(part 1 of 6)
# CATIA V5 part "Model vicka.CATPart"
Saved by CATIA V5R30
Part number: Tvarnik_tvarnice
Material "PVC": density 1400 kg/m3, Young's modulus 3e+09 Pa, Poisson ratio 0.4, thermal expansion 9e-05 1/K
Bounding box of the stored display mesh (mm): x -12.5 to 2.6, y -74.249 to 75.778, z -73.2 to 71.421
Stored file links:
  E:\Bakalarka\Model\Vicko.CATPart
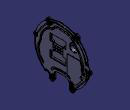
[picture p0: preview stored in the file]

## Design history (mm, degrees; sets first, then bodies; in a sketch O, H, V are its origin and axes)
WSupportSet1
Body1 "Vicko" (main body), material "PVC"
  Sketch1 on yz-plane, origin (0, 0, 0), H (0, 1, 0), V (0, 0, 1)
    circle A1 centre (0, 0) radius 71.425
    radius A1 = 71.425
  Pad1: profile Sketch1, direction (1, 0, 0), length 1.6
  Sketch2 on end face of Pad1, origin (1.6, 0, 0), H (0, 1, 0), V (0, 0, 1)
    point P1 (0, -48.7537)
    point P2 (4.8105, -22.8909)
    point P3 (2.4617, -31.9059)
    line L1 (19.7, -77.5722) -> (19.7, -54.5084)
    point P5 (19.7, -54.5084)
    point P6 (19.7, -54.5084)
    arc A1 centre (10.55, -54.5084) radius 9.15 from (19.7, -54.5084) to (12.2, -45.5084) ccw
    point P8 (12.2, -45.5084)
    point P9 (-13.7, -45.2166)
    arc A2 centre (-12.6167, -52.2166) radius 7.0833 from (-13.7, -45.2166) to (-19.7, -52.2166) ccw
    point P11 (-19.7, -52.2166)
    line L2 (-19.7, -52.2166) -> (-19.7, -86.8828)
    line L3 (-19.7, -86.8828) -> (19.7, -86.8828)
    point P13 (19.7, -86.8828)
    line L4 (19.7, -86.8828) -> (19.7, -77.5722)
    arc A3 centre (-1.5593, -117.2) radius 73 from (-13.7, -45.2166) to (12.2, -45.5084) cw
    point P15 (-13.7, -45.2166)
    distance L1 V = 19.7
    length L3 = 39.4
    distance P11 P5 H = 39.4
    distance P6 P5 H = 0
    distance P6 P5 = 0
    distance P9 P15 H = 0
    distance P9 P15 V = 0
    distance A3 H = 44.2
    distance L3 H = 86.8828
    distance P8 P5 H = 7.5
    distance P5 P8 V = 9
    distance P11 P9 V = 7
    length L2 = 34.6662
    distance P11 P9 H = 6
    radius A3 = 73
    vertical: L1 V, L4 V
    coincidence: P13 L1
    horizontal: L3 H
    tangency: A1 L1, A2 L2
  Pocket1: profile Sketch2, direction (-1, 0, 0), length 1.6
  Sketch3 on start face of Pad1, origin (0, 0, 0), H (0, -1, 0), V (0, 0, 1)
    line L1 (19.7, -73.2) -> (31.75, -73.2)
    line L2 (31.75, -73.2) -> (31.75, -53.2)
    line L3 (31.75, -53.2) -> (19.7, -53.2)
    line L4 (19.7, -53.2) -> (19.7, -73.2)
    reference projected line E1 (19.7, -52.2166) -> (19.7, -68.6545) from edge [face of Pocket1 from Sketch2.L2 | start face of Pad1]
    reference projected arc E2 centre (1.5593, -117.2) radius 73 from (13.7, -45.2166) to (-12.2, -45.5084) ccw from edge [face of Pocket1 from Sketch2.A3 | start face of Pad1]
    distance L4 E1 = 0
    distance E2 L1 = 29
    length L1 = 12.05
    distance L3 L1 = 20
    horizontal: L1 H, L3 H
    vertical: L2 V, L4 V
  Pad2: profile Sketch3, direction (1, 0, 0), length 1.6
  Sketch4 on face of Pad2, origin (0, 0, 0), H (0, -1, 0), V (0, 0, 1)
    line L1 (-34.7, -73.2) -> (-19.7, -73.2)
    line L2 (-19.7, -73.2) -> (-19.7, -58.2)
    line L3 (-19.7, -58.2) -> (-34.7, -58.2)
    line L4 (-34.7, -58.2) -> (-34.7, -73.2)
    reference projected line E1 (-19.7, -68.6545) -> (-19.7, -54.5084) from edge [face of Pocket1 from Sketch2.L1 | start face of Pad1]
    reference projected line E2 (19.7, -73.2) -> (31.75, -73.2) from edge [face of Pad2 from Sketch3.L1 | face of Pad2]
    distance L2 E1 = 0
    distance L1 E2 = 0
    length L4 = 15
    length L1 = 15
    horizontal: L1 H, L3 H
    vertical: L2 V, L4 V
  Pad3: profile Sketch4, direction (1, 0, 0), length 1.6
  Sketch5 on face of Pad3, origin (0, 0, 0), H (0, -1, 0), V (0, 0, 1)
    circle A1 centre (38.7, -63.15) radius 7
    point P1 (38.7, -63.15)
    reference projected line E1 (19.7, -52.2166) -> (19.7, -73.2) from edge [face of Pad2 | face of Pad2]
    reference projected arc E2 centre (1.5593, -117.2) radius 73 from (13.7, -45.2166) to (-12.2, -45.5084) ccw from edge [face of Pocket1 from Sketch2.A3 | start face of Pad1]
    radius A1 = 7
    distance P1 E1 = 19
    distance A1 E2 V = 25.95
  Pocket2: profile Sketch5, direction (1, 0, 0), length 12
  Sketch6 on face of Pad3, origin (0, 0, 0), H (0, -1, 0), V (0, 0, 1)
    line L1 (42.5952, -57.3339) -> (43.3048, -57.6709)
    point P1 (42.5952, -57.3339)
    point P2 (43.3048, -57.6709)
    line L2 (43.3048, -57.6709) -> (44.5756, -55.8081)
    point P3 (44.5756, -55.8081)
    line L3 (42.5952, -57.3339) -> (44.5756, -55.8081)
    reference projected point E1 (42.5952, -57.3339) from vertex [face of Pad3 | face of Pad1 from Sketch1.A1 | face of Pocket2 from Sketch5.A1]
    reference projected circle E2 centre (0, 0) radius 71.425 from edge [face of Pad3 | face of Pad1 from Sketch1.A1]
    distance L1 E1 = 0
    length L3 = 2.5
    distance E2 P1 = 0
    distance P3 E2 = 0
    distance L3 P2 = 0.7
    length L2 = 2.255
  Pad4: profile Sketch6, direction (1, 0, 0), length 1.6
  Fillet1: radius 0.5, on edge [face of Pad4 from Sketch6.L1 | face of Pad4 from Sketch6.L2]
  Fillet2: radius 0.5, on edge [face of Pad4 from Sketch6.L2 | face of Pad1 from Sketch1.A1]
  Sketch7 on face of Pad4, origin (0, 0, 0), H (0, -1, 0), V (0, 0, 1)
    line L1 (25.725, -73.2) -> (33.6, -68.8429)
    point P1 (25.725, -73.2)
    point P2 (33.6, -68.8429)
    line L2 (31.75, -62.8) -> (25.725, -73.2)
    arc A1 centre (39.7026, -63.67) radius 8 from (31.75, -62.8) to (33.6, -68.8429) ccw
    point P4 (31.75, -62.8)
    point P5 (33.6, -68.8429)
    reference projected line E1 (19.7, -52.2166) -> (19.7, -73.2) from edge [face of Pad2 | face of Pad2]
    reference projected line E2 (19.7, -73.2) -> (31.75, -73.2) from edge [face of Pad2 from Sketch3.L1 | face of Pad4]
    reference projected line E3 (31.75, -73.2) -> (31.75, -53.2) from edge [face of Pad2 from Sketch3.L2 | face of Pad4]
    radius A1 = 8
    distance P5 P2 = 0
    distance P1 E1 = 6.025
    distance P2 E1 = 13.9
    distance P1 E2 = 0
    length L1 = 9
    distance P4 P1 V = 10.4
    distance P4 E3 = 0
  Pad5: profile Sketch7, direction (1, 0, 0), length 1.6
  Sketch8 on face of Pad5, origin (0, 0, 0), H (0, -1, 0), V (0, 0, 1)
    projected line E1 (25.725, -73.2) -> (33.6, -68.8429) from Sketch7.L1
    projected line E2 (25.725, -73.2) -> (31.75, -69.8665) from Sketch7.L1
    point P1 (25.725, -73.2)
    projected line E3 (19.7, -73.2) -> (31.75, -73.2) from edge [face of Pad2 from Sketch3.L1 | face of Pad5]
    projected line E4 (25.725, -73.2) -> (31.75, -73.2) from edge [face of Pad2 from Sketch3.L1 | face of Pad5]
    point P4 (31.75, -73.2)
    projected line E5 (31.75, -73.2) -> (31.75, -69.8665) from edge [face of Pad2 from Sketch3.L2 | face of Pad5]
    point P5 (31.75, -73.2)
    point P7 (25.725, -73.2)
    coincidence: E1 P7, P1 P7, P4 P5
  Pocket3: profile Sketch8, direction (1, 0, 0), length 1.6
  Sketch9 on face of Pad5, origin (0, 0, 0), H (0, -1, 0), V (0, 0, 1)
    arc A1 centre (25.7, -67.2) radius 6 from (19.7, -67.2) to (25.725, -73.1999) ccw
    projected line E1 (19.7, -73.2) -> (25.725, -73.2) from edge [face of Pad2 from Sketch3.L1 | face of Pad5]
    point P2 (19.7, -73.2)
    projected line E2 (19.7, -52.2166) -> (19.7, -73.2) from edge [face of Pad2 | face of Pad5]
    projected line E3 (19.7, -67.2) -> (19.7, -73.2) from edge [face of Pad2 | face of Pad5]
    point P5 (19.7, -73.2)
    point P6 (19.7, -67.2)
    point P7 (25.725, -73.1999)
    point P8 (19.7, -67.2)
    distance A1 E2 = 0
    distance A1 E1 = 0
    radius A1 = 6
    coincidence: A1 P6, E1 P7, E2 P8, P2 P5, P6 P8
  Pocket4: profile Sketch9, direction (1, 0, 0), length 1.6
  Sketch10 on face of Pad5, origin (0, 0, 0), H (0, -1, 0), V (0, 0, 1)
    reference projected line E1 (-34.7, -73.2) -> (-19.7, -73.2) from edge [face of Pad3 from Sketch4.L1 | face of Pad5]
    reference projected line E2 (-19.7, -73.2) -> (-19.7, -54.5084) from edge [face of Pad3 | face of Pad3]
    arc A1 centre (-27.2, -65.7) radius 7 from (-34.2, -65.7) to (-29.054, -72.45) ccw
    line L1 (-27.2, -73.2) -> (-29.054, -72.45)
    point P2 (-27.2, -73.2)
    point P3 (-29.054, -72.45)
    arc A2 centre (-39.6, -65.7) radius 5.4 from (-34.2, -65.7) to (-34.7, -63.4306) ccw
    point P5 (-34.2, -65.7)
    point P6 (-37.9, -60.5402)
    point P7 (-34.7, -63.4306)
    line L2 (-27.2, -73.2) -> (-34.7, -73.2)
    line L3 (-34.7, -73.2) -> (-34.7, -63.4306)
    point P9 (-34.7, -63.4306)
    radius A1 = 7
    distance P5 E1 = 7.5
    length L1 = 2
    distance P2 E2 = 7.5
    radius A2 = 5.4
    radius A1 = 7 (reference)
    length L2 = 7.5
    distance L2 E1 = 0
    distance P3 L2 = 0.75
    length L3 = 9.7694
    tangency: A2 A1
    horizontal: L2 H
    coincidence: P9 A2, P7 P9
    vertical: L3 V
  Pocket5: profile Sketch10, direction (1, 0, 0), length 1.6
  Sketch11 on face of Pad5, origin (0, 0, 0), H (0, -1, 0), V (0, 0, 1)
    arc A1 centre (-26.95, -65.95) radius 7.25 from (-26.95, -73.2) to (-19.7, -65.95) ccw
    reference projected line E1 (-34.7, -73.2) -> (-19.7, -73.2) from edge [face of Pad3 from Sketch4.L1 | face of Pad5]
    reference projected line E2 (-19.7, -73.2) -> (-19.7, -54.5084) from edge [face of Pad3 | face of Pad3]
    projected line E3 (-19.7, -73.2) -> (-19.7, -54.5084) from edge [face of Pad3 | face of Pad5]
    projected line E4 (-19.7, -73.2) -> (-19.7, -65.95) from edge [face of Pad3 | face of Pad5]
    point P4 (-26.9896, -73.1999)
    point P5 (-19.7, -65.95)
    line L1 (-19.7, -73.2) -> (-26.95, -73.2)
    point P6 (-26.95, -73.2)
    point P7 (-26.95, -73.2)
    point P8 (-19.7, -65.95)
    distance A1 E1 = 0
    distance A1 E2 = 0
    radius A1 = 7.25
    coincidence: A1 P5, P4 A1, P6 A1, E3 P8, L1 P7, P5 P8, P6 P7
    tangency: L1 A1
  Pocket6: profile Sketch11, direction (1, 0, 0), length 1.6
  Sketch12 on face of Pad5, origin (0, 0, 0), H (0, -1, 0), V (0, 0, 1)
    point P1 (-72.1976, -12.4535)
    reference projected circle E1 centre (0, 0) radius 71.425 from edge [face of Pad5 | face of Pad1 from Sketch1.A1]
    arc A1 centre (-69.7785, -6.9628) radius 6 from (-72.1976, -12.4535) to (-75.4588, -5.0305) cw
    line L1 (-75.4588, -5.0305) -> (-70.95, 8.2236)
    point P4 (-70.95, 8.2236)
    line L2 (-72.1976, -12.4535) -> (-69.95, -14.4405)
    point P5 (-72.1976, -12.4535)
    point P6 (-69.95, -14.4405)
    reference projected point E2 (-26.95, -73.2) from vertex [face of Pad5 | face of Pad3 from Sketch4.L1 | face of Pocket6 from Sketch11.A1]
    projected arc E3 centre (0, 0) radius 71.425 from (44.634, -55.7614) to (-34.7, -62.4295) ccw from edge [face of Pad5 | face of Pad1 from Sketch1.A1]
    projected arc E4 centre (0, 0) radius 71.425 from (-70.95, 8.2236) to (-69.95, -14.4405) ccw from edge [face of Pad5 | face of Pad1 from Sketch1.A1]
    point P9 (-70.95, 8.2236)
    radius A1 = 6
    distance P4 E1 = 0
    distance A1 E1 = 4.7
    distance P6 E2 H = 43
    distance P5 P1 = 0
    distance P4 E2 H = 44
    length L1 = 14
    length L2 = 3
    tangency: L1 A1
    coincidence: P5 A1, L1 P9
  Pad6: profile Sketch12, direction (1, 0, 0), length 1.6
  Fillet3: radius 0.5, on edge [face of Pad6 from Sketch12.L2 | face of Pad6 from Sketch12.A1]
  Fillet4: radius 1, on edge [face of Pad1 from Sketch1.A1 | face of Pad6 from Sketch12.L2]
  Sketch13 on face of Pad6, origin (0, 0, 0), H (0, -1, 0), V (0, 0, 1)
    arc A1 centre (-69.5316, 12.3887) radius 4.4 from (-70.95, 8.2236) to (-65.7164, 14.5806) ccw
    point P2 (-70.95, 8.2236)
    reference projected arc E1 centre (0, 0) radius 71.425 from (44.5756, -55.8081) to (-34.7, -62.4295) ccw from edge [face of Pad6 | face of Pad1 from Sketch1.A1]
    reference projected point E2 (-70.95, 8.2236) from vertex [element of Sketch12 | element of Sketch12]
    line L1 (-65.7164, 14.5806) -> (-68.6555, 19.6964)
    point P4 (-68.6555, 19.6964)
    projected arc E3 centre (0, 0) radius 71.425 from (44.634, -55.7614) to (-70.95, 8.2236) ccw from edge [face of Pad6 | face of Pad1 from Sketch1.A1]
    projected arc E4 centre (0, 0) radius 71.425 from (-68.6555, 19.6964) to (-70.95, 8.2236) ccw from edge [face of Pad6 | face of Pad1 from Sketch1.A1]
    distance P2 E1 = 0
    radius A1 = 4.4
    distance P2 E2 = 0
    distance P4 P2 = 11.7
    length L1 = 5.9
    tangency: L1 A1
  Pocket7: profile Sketch13, direction (1, 0, 0), length 1.6
  Sketch14 on face of Pad6, origin (0, 0, 0), H (0, -1, 0), V (0, 0, 1)
    arc A1 centre (-38.2049, 58.0324) radius 6 from (-43.95, 56.3021) to (-34.3447, 62.6257) cw
    point P2 (-43.95, 56.3021)
    point P3 (-34.3447, 62.6257)
    reference projected point E1 (-26.95, -73.2) from vertex [face of Pad5 | face of Pad3 from Sketch4.L1 | face of Pocket6 from Sketch11.A1]
    projected arc E2 centre (0, 0) radius 71.425 from (44.634, -55.7614) to (-68.6555, 19.6964) ccw from edge [face of Pad6 | face of Pad1 from Sketch1.A1]
    projected arc E3 centre (0, 0) radius 71.425 from (-34.3447, 62.6257) to (-43.95, 56.3021) ccw from edge [face of Pad6 | face of Pad1 from Sketch1.A1]
    distance P2 E1 H = 17
    radius A1 = 6
    distance P2 P3 = 11.5
  Pad7: profile Sketch14, direction (1, 0, 0), length 1.6
  Fillet5: radius 2, on edge [face of Pad7 from Sketch14.A1 | face of Pad1 from Sketch1.A1]; edge [face of Pad1 from Sketch1.A1 | face of Pad7 from Sketch14.A1]
  Sketch15 on face of Pad7, origin (0, 0, 0), H (0, -1, 0), V (0, 0, 1)
    arc A1 centre (35.5625, 59.6882) radius 6 from (31.5, 64.1037) to (41.3794, 58.2175) cw
    point P2 (31.5, 64.1037)
    point P3 (41.3794, 58.2175)
    reference projected line E1 (19.7, -52.2166) -> (19.7, -73.2) from edge [face of Pad2 | face of Pad7]
    projected arc E2 centre (0, 0) radius 71.425 from (44.634, -55.7614) to (-33.2826, 63.1965) ccw from edge [face of Pad7 | face of Pad1 from Sketch1.A1]
    projected arc E3 centre (0, 0) radius 71.425 from (41.3794, 58.2175) to (31.5, 64.1037) ccw from edge [face of Pad7 | face of Pad1 from Sketch1.A1]
    distance P2 E1 = 11.8
    radius A1 = 6
    distance P3 P2 = 11.5
  Pad8: profile Sketch15, direction (1, 0, 0), length 1.6
  Fillet6: radius 2, on edge [face of Pad1 from Sketch1.A1 | face of Pad8 from Sketch15.A1]; edge [face of Pad8 from Sketch15.A1 | face of Pad1 from Sketch1.A1]
  Sketch16 on face of Pad8, origin (0, 0, 0), H (0, -1, 0), V (0, 0, 1)
    arc A1 centre (68.2522, 13.0002) radius 6 from (71.0117, 7.6724) to (68.86, 18.9693) ccw
    point P2 (71.0117, 7.6724)
    point P3 (68.86, 18.9693)
    reference projected arc E1 centre (0, 0) radius 71.425 from (44.5756, -55.8081) to (-34.7, -62.4295) ccw from edge [face of Pad8 | face of Pad1 from Sketch1.A1]
    reference projected line E2 (19.7, -52.2166) -> (19.7, -73.2) from edge [face of Pad2 | face of Pad8]
    projected arc E3 centre (0, 0) radius 71.425 from (44.634, -55.7614) to (42.3563, 57.5107) ccw from edge [face of Pad8 | face of Pad1 from Sketch1.A1]
    projected arc E4 centre (0, 0) radius 71.425 from (71.0117, 7.6724) to (68.86, 18.9693) ccw from edge [face of Pad8 | face of Pad1 from Sketch1.A1]
    point P6 (71.0117, 7.6724)
    radius A1 = 6
    distance P2 E1 = 0
    distance P2 E2 = 51.3117
    distance P2 P3 = 11.5
    coincidence: A1 P6
  Pad9: profile Sketch16, direction (1, 0, 0), length 1.6
  Fillet7: radius 2, on edge [face of Pad1 from Sketch1.A1 | face of Pad9 from Sketch16.A1]; edge [face of Pad9 from Sketch16.A1 | face of Pad1 from Sketch1.A1]
  Sketch17 on face of Pad9, origin (0, 0, 0), H (0, -1, 0), V (0, 0, 1)
    arc A1 centre (-26.45, -66.45) radius 6.25 from (-32.7, -66.45) to (-20.2, -66.45) ccw
    reference projected line E1 (-19.7, -73.2) -> (-19.7, -54.5084) from edge [face of Pad3 | face of Pad9]
    reference projected point E2 (-26.95, -73.2) from vertex [face of Pad5 | face of Pad3 from Sketch4.L1 | face of Pocket6 from Sketch11.A1]
    point P2 (-32.7, -66.45)
    line L1 (-32.7, -66.45) -> (-32.7, -55.45)
    point P3 (-32.7, -55.45)
    arc A2 centre (-32.306, -33.4535) radius 22 from (-32.7, -55.45) to (-49.1519, -47.6033) cw
    point P5 (-49.1519, -47.6033)
    line L2 (-49.1519, -47.6033) -> (-60.2, -34.45)
    point P6 (-66.9743, -26.3849)
    point P7 (-62.7353, -16.2331)
    point P8 (-66.9743, -26.3849)
    line L3 (-69.1412, -16.0776) -> (-69.1412, -16.0775)
    arc A3 centre (-74.0342, -17.1062) radius 5 from (-69.1412, -16.0775) to (-72.0998, -12.4956) ccw
    line L4 (-72.0998, -12.4956) -> (-72.0998, -12.4956)
    arc A4 centre (-69.7785, -6.9628) radius 6 from (-72.0998, -12.4956) to (-73.6417, -2.372) cw
    point P13 (-69.7785, -6.9628)
    line L5 (-73.6417, -2.372) -> (-66.0256, 4.0372)
    point P15 (-66.0256, 4.0372)
    point P16 (-66.0256, 4.0372)
    arc A5 centre (39.9635, -25.3959) radius 110 from (-66.0256, 4.0372) to (-47.7674, 40.9614) cw
    point P18 (-47.7674, 40.9614)
    arc A6 centre (-63.7184, 53.0264) radius 20 from (-47.7674, 40.9614) to (-44.0926, 56.8771) ccw
    arc A7 centre (-38.2049, 58.0324) radius 6 from (-44.0926, 56.8771) to (-35.5164, 63.3963) cw
    point P21 (-38.2049, 58.0324)
    arc A8 centre (-26.5547, 81.2761) radius 20 from (-35.5164, 63.3963) to (-20.6839, 62.1572) ccw
    point P24 (-20.6839, 62.1572)
    arc A9 centre (-35.3609, 109.9545) radius 50 from (-20.6839, 62.1572) to (-17.5109, 63.2493) ccw
    arc A10 centre (-10.3709, 44.5672) radius 20 from (-17.5109, 63.2493) to (-11.2817, 64.5465) cw
    point P28 (-11.2817, 64.5465)
    point P29 (12.1273, 65.6137)
    point P30 (33.2273, 65.2151)
    arc A11 centre (35.5625, 59.6882) radius 6 from (33.2273, 65.2151) to (41.2484, 57.7725) cw
    point P31 (35.5625, 59.6882)
    point P32 (41.2484, 57.7725)
    point P33 (68.7354, 18.9807)
    arc A12 centre (68.2522, 13.0002) radius 6 from (68.7354, 18.9807) to (72.7846, 9.0686) cw
    point P34 (68.2522, 13.0002)
    arc A13 centre (80.3386, 2.516) radius 10 from (72.7846, 9.0686) to (70.3837, 1.5673) ccw
    arc A14 centre (10.6543, -4.1251) radius 60 from (70.3837, 1.5673) to (66.5615, -25.9055) cw
    point P39 (66.5615, -25.9055)
    arc A15 centre (15.8905, -6.165) radius 54.3805 from (66.5615, -25.9055) to (36.0987, -56.6513) cw
    arc A16 centre (38.7, -63.15) radius 7 from (36.0987, -56.6513) to (31.7249, -63.7401) ccw
    point P43 (31.7249, -63.7401)
    point P44 (31.7249, -63.7401)
    arc A17 centre (26.2, -66.08) radius 6 from (31.7249, -63.7401) to (20.2, -66.08) cw
    point P46 (20.2, -66.08)
    line L6 (20.2, -66.08) -> (20.2, -52.2166)
    point P47 (20.2, -52.2166)
    arc A18 centre (13.2, -52.2166) radius 7 from (20.2, -52.2166) to (14.4551, -45.3301) ccw
    arc A19 centre (1.3665, -117.1471) radius 73 from (14.4551, -45.3301) to (-12.8293, -45.5407) ccw
    arc A20 centre (-11.0499, -54.516) radius 9.15 from (-12.8293, -45.5407) to (-20.1999, -54.5179) ccw
    point P53 (-20.2, -54.5179)
    line L7 (-20.2, -54.5179) -> (-20.2, -66.45)
    point P54 (-20.2, -66.45)
    reference projected arc E3 centre (-10.55, -54.5084) radius 9.15 from (-12.2, -45.5084) to (-19.7, -54.5084) ccw from edge [face of Pocket1 from Sketch2.A1 | face of Pad9]
    reference projected arc E4 centre (12.6167, -52.2166) radius 7.0833 from (19.7, -52.2166) to (13.7, -45.2166) ccw from edge [face of Pocket1 from Sketch2.A2 | face of Pad9]
    reference projected line E5 (19.7, -52.2166) -> (19.7, -73.2) from edge [face of Pad2 | face of Pad9]
    reference projected arc E6 centre (38.7, -63.15) radius 7 from (42.5952, -57.3339) to (31.7053, -62.8771) ccw from edge [face of Pad9 | face of Pocket2 from Sketch5.A1]
    reference projected point E7 (19.7, -52.2166) from vertex [face of Pad2 | face of Pad2 | face of Pocket1 from Sketch2.A2]
    reference projected line E8 (25.725, -73.2) -> (33.6, -68.8429) from edge [face of Pocket3 | face of Pad9]
    reference projected arc E9 centre (1.5593, -117.2) radius 73 from (13.7, -45.2166) to (-12.2, -45.5084) ccw from edge [face of Pocket1 from Sketch2.A3 | start face of Pad1]
    arc A21 centre (-28.0396, -7.4369) radius 42 from (-60.2, -34.45) to (-69.1412, -16.0776) cw
    point P55 (-60.2, -34.45)
    reference projected arc E10 centre (0, 0) radius 71.425 from (31.75, -63.9802) to (-34.7, -62.4295) ccw from edge [face of Pad9 | face of Pad1 from Sketch1.A1]
    reference projected arc E11 centre (-69.7785, -6.9628) radius 6 from (-75.4588, -5.0305) to (-72.1976, -12.4535) ccw from edge [face of Pad6 from Sketch12.A1 | face of Pad9]
    reference projected arc E12 centre (-38.2049, 58.0324) radius 6 from (-34.3447, 62.6257) to (-43.95, 56.3021) ccw from edge [face of Pad7 from Sketch14.A1 | face of Pad9]
    reference projected arc E13 centre (0, 0) radius 71.425 from (44.634, -55.7614) to (-70.95, 8.2236) ccw from edge [face of Pad9 | face of Pad1 from Sketch1.A1]
    line L8 (-11.2817, 64.5465) -> (12.1273, 65.6137)
    arc A22 centre (13.0382, 45.6344) radius 20 from (12.1273, 65.6137) to (19.8826, 64.4268) cw
    point P59 (19.8826, 64.4268)
    point P60 (19.8826, 64.4268)
    arc A23 centre (25.4433, 83.6382) radius 20 from (19.8826, 64.4268) to (33.2273, 65.2151) ccw
    point P62 (33.2273, 65.2151)
    reference projected arc E15 centre (35.5625, 59.6882) radius 6 from (41.3794, 58.2175) to (31.5, 64.1037) ccw from edge [face of Pad8 from Sketch15.A1 | face of Pad9]
    arc A24 centre (56.2086, 56.68) radius 15 from (41.2484, 57.7725) to (45.6622, 46.0136) ccw
    point P64 (45.6622, 46.0136)
    reference projected arc E16 centre (68.2522, 13.0002) radius 6 from (71.0117, 7.6724) to (68.86, 18.9693) ccw from edge [face of Pad9 from Sketch16.A1 | face of Pad9]
    arc A25 centre (72.4489, 33.5138) radius 15 from (68.7354, 18.9807) to (58.8572, 27.1683) cw
    point P66 (68.7354, 18.9807)
    point P67 (58.8572, 27.1683)
    arc A26 centre (0.5413, 0.379) radius 64.1748 from (58.8572, 27.1683) to (45.6622, 46.0136) ccw
    point P69 (45.6622, 46.0136)
    point P70 (-32.7, -66.45)
    point P71 (-20.2, -66.45)
    radius A1 = 6.25
    distance A1 E1 = 0.5
    distance A1 E2 V = 0.5
    distance P3 E1 = 13
    distance P53 E1 = 0.5
    radius A20 = 9.15
    distance A20 E3 = 0.5
    radius A18 = 7
    distance A18 E4 = 0.5
    radius A19 = 73
    distance P46 E5 = 0.5
    radius A17 = 6
    radius A16 = 7
    distance E6 A16 = 0
    distance P44 P43 = 0
    distance P47 E7 V = 0
    distance A17 E8 = 0
    distance A19 E9 = 0.2
    radius A2 = 22
    distance P5 E10 = 3
    distance L1 P55 = 27.5
    length L1 = 11
    radius A21 = 42
    distance P55 P3 V = 21
    radius A3 = 5
    radius A4 = 6
    distance A4 E11 = 0
    distance P15 P13 V = 11
    radius A7 = 6
    distance A7 E12 = 0
    radius A6 = 20
    distance E13 P18 = 8.5
    distance P15 P16 = 0
    length L5 = 9.9541
    radius A5 = 110
    distance P29 E10 = 4.7
    distance P28 E10 = 5.9
    distance P28 P21 = 27.7
    distance P29 P21 = 50.9
    radius A10 = 20
    radius A9 = 50
    radius A8 = 20
    distance P24 P21 = 18
    distance P60 P59 = 0
    distance P62 P30 = 0
    distance A11 E15 = 0
    radius A11 = 6
    radius A23 = 20
    distance P59 E10 = 4
    radius A22 = 20
    radius A24 = 15
    distance P64 E10 = 6.6
    distance P64 P31 = 17
    distance P31 P32 H = 5.686
    radius A12 = 6
    distance A12 E16 = 0
    distance P69 P64 = 0
    radius A25 = 15
    distance P67 P34 = 17
    distance P67 E10 = 6.6
    distance P66 P33 = 0
    distance P33 P34 H = 0.4832
    radius A13 = 10
    distance P39 E10 = 0
    radius A14 = 60
    radius A15 = 54.3805
    coincidence: P2 A1, P8 L2, P54 A1, L2 P6, L3 P8, P8 P6, P66 A12, P67 A15, L7 P71, L1 P70, P2 P70, P54 P71
    tangency: L1 A1, L2 A2, A3 L3, L4 A3, A4 L4, L5 A4, A6 A5, A7 A6, A8 A7, A9 A8, A10 A9, A13 A12, A14 A13, A15 A14, A16 A15, L6 A17, A18 L6, A19 A18, A20 A19, L7 A1, A21 L2, A21 L3, A3 A21, A3 A4, L8 A10, A22 L8, A23 A11, A26 A24
  Pad10: profile Sketch17, direction (-1, 0, 0), length 3.8
  Sketch18 on end face of Pad10, origin (-3.8, 0, 0), H (0, -1, 0), V (0, 0, 1)
    line L1 (-31.2, -54.7) -> (-15.7, -45.4718)
    point P1 (-31.2, -54.7)
    point P2 (-15.7, -45.4718)
    point P3 (-15.7, -45.4718)
    reference projected arc E1 centre (-26.45, -66.45) radius 6.25 from (-32.7, -66.45) to (-20.2, -66.45) ccw from edge [face of Pad10 from Sketch17.A1 | end face of Pad10]
    reference projected line E2 (-32.7, -55.45) -> (-32.7, -66.45) from edge [face of Pad10 from Sketch17.L1 | end face of Pad10]
    reference projected arc E3 centre (-11.0499, -54.516) radius 9.15 from (-12.8293, -45.5407) to (-20.1999, -54.5179) ccw from edge [face of Pad10 from Sketch17.A20 | end face of Pad10]
    arc A1 centre (-12.119, -51.4865) radius 7 from (-15.7, -45.4718) to (-12.8415, -44.5239) cw
    point P5 (-12.8415, -44.5239)
    reference projected arc E4 centre (1.3665, -117.1471) radius 73 from (14.4551, -45.3301) to (-12.8293, -45.5407) ccw from edge [face of Pad10 from Sketch17.A19 | end face of Pad10]
    arc A2 centre (1.1745, -116.1657) radius 73 from (-12.8415, -44.5239) to (15.9847, -44.6839) cw
    point P7 (0, -43.1752)
    arc A3 centre (14.3617, -52.5175) radius 8 from (15.9847, -44.6839) to (21.4455, -48.8) cw
    arc A4 centre (32.0711, -43.2237) radius 12 from (21.4455, -48.8) to (36.6462, -54.3173) ccw
    point P12 (36.6462, -54.3173)
    arc A5 centre (17.6228, -8.0776) radius 50 from (36.6462, -54.3173) to (66.9135, -16.4694) ccw
    point P14 (66.9135, -16.4694)
    arc A6 centre (37.3391, -11.4343) radius 30 from (66.9135, -16.4694) to (64.4029, 1.5097) ccw
    point P16 (64.4029, 1.5097)
    reference projected arc E5 centre (13.2, -52.2166) radius 7 from (20.2, -52.2166) to (14.4551, -45.3301) ccw from edge [face of Pad10 from Sketch17.A18 | end face of Pad10]
    reference projected arc E6 centre (38.7, -63.15) radius 7 from (36.0987, -56.6513) to (31.7249, -63.7401) ccw from edge [face of Pad10 from Sketch17.A16 | end face of Pad10]
    reference projected arc E7 centre (15.8905, -6.165) radius 54.3805 from (36.0987, -56.6513) to (66.5615, -25.9055) ccw from edge [face of Pad10 from Sketch17.A15 | end face of Pad10]
    reference projected arc E8 centre (68.2522, 13.0002) radius 6 from (72.7846, 9.0686) to (68.7354, 18.9807) ccw from edge [face of Pad10 from Sketch17.A12 | end face of Pad10]
    reference projected line E9 (20.2, -52.2166) -> (20.2, -66.08) from edge [face of Pad10 from Sketch17.L6 | end face of Pad10]
    reference projected arc E10 centre (72.4489, 33.5138) radius 15 from (58.8572, 27.1683) to (68.7354, 18.9807) ccw from edge [face of Pad10 from Sketch17.A25 | end face of Pad10]
    arc A7 centre (80.9158, 12.7935) radius 20 from (64.4029, 1.5097) to (60.9311, 13.575) cw
    point P18 (64.4029, 1.5097)
    point P19 (60.9311, 13.575)
    arc A8 centre (45.9426, 14.1611) radius 15 from (60.9311, 13.575) to (60.8265, 16.0232) ccw
    point P21 (60.8265, 16.0232)
    reference projected arc E11 centre (0, 0) radius 71.425 from (44.634, -55.7614) to (41.3794, 58.2175) ccw from edge [face of Pad9 | face of Pad1 from Sketch1.A1]
    reference projected arc E15 centre (0, 0) radius 71.425 from (44.634, -55.7614) to (41.3794, 58.2175) ccw from edge [face of Pad9 | face of Pad1 from Sketch1.A1]
    arc A9 centre (-34.9988, -12.569) radius 100 from (60.8265, 16.0232) to (58.9599, 21.6622) ccw
    point P23 (58.9599, 21.6622)
    reference projected arc E19 centre (0.5413, 0.379) radius 64.1748 from (58.8572, 27.1683) to (45.6622, 46.0136) ccw from edge [face of Pad10 from Sketch17.A26 | end face of Pad10]
    arc A10 centre (2.5847, 1.1235) radius 60 from (58.9599, 21.6622) to (38.3483, 49.2998) ccw
    arc A11 centre (31.8974, 41.6588) radius 10 from (38.3483, 49.2998) to (31.7183, 51.6572) ccw
    point P27 (38.3483, 49.2998)
    point P28 (31.7183, 51.6572)
    arc A12 centre (31.5751, 59.656) radius 8 from (31.7183, 51.6572) to (24.9702, 55.1421) cw
    point P30 (24.9702, 55.1421)
    reference projected arc E20 centre (35.5625, 59.6882) radius 6 from (41.2484, 57.7725) to (33.2273, 65.2151) ccw from edge [face of Pad10 from Sketch17.A11 | end face of Pad10]
    arc A13 centre (8.752, 43.4387) radius 20 from (24.9702, 55.1421) to (7.5795, 63.4043) ccw
    point P32 (7.5795, 63.4043)
    reference projected arc E21 centre (56.2086, 56.68) radius 15 from (41.2484, 57.7725) to (45.6622, 46.0136) ccw from edge [face of Pad10 from Sketch17.A24 | end face of Pad10]
    reference projected arc E22 centre (25.4433, 83.6382) radius 20 from (19.8826, 64.4268) to (33.2273, 65.2151) ccw from edge [face of Pad10 from Sketch17.A23 | end face of Pad10]
    reference projected line E23 (12.1273, 65.6137) -> (-11.2817, 64.5465) from edge [face of Pad10 from Sketch17.L8 | end face of Pad10]
    line L2 (7.5795, 63.4043) -> (-14.3827, 62.1145)
    point P33 (-14.3827, 62.1145)
    arc A14 centre (-7.435, 25.3654) radius 37.4 from (-14.3827, 62.1145) to (-33.469, 52.2168) ccw
    point P35 (-33.469, 52.2168)
    arc A15 centre (-40.4356, 56.1495) radius 8 from (-33.469, 52.2168) to (-37.6543, 48.6485) cw
    point P37 (-37.6543, 48.6485)
    arc A16 centre (26.1946, -18.2866) radius 92.504 from (-37.6543, 48.6485) to (-64.4065, 0.3795) ccw
    point P39 (-64.4065, 0.3795)
    reference projected arc E24 centre (-10.3709, 44.5672) radius 20 from (-11.2817, 64.5465) to (-17.5109, 63.2493) ccw from edge [face of Pad10 from Sketch17.A10 | end face of Pad10]
    reference projected arc E25 centre (-38.2049, 58.0324) radius 6 from (-35.5164, 63.3963) to (-44.0926, 56.8771) ccw from edge [face of Pad10 from Sketch17.A7 | end face of Pad10]
    reference projected arc E26 centre (39.9635, -25.3959) radius 110 from (-47.7674, 40.9614) to (-66.0256, 4.0372) ccw from edge [face of Pad10 from Sketch17.A5 | end face of Pad10]
    arc A17 centre (-44.4672, -1.177) radius 20 from (-64.4065, 0.3795) to (-64.0844, -5.0714) ccw
    point P41 (-64.4065, 0.3795)
    point P42 (-64.0844, -5.0714)
    point P43 (-64.0439, -4.9422)
    point P44 (-66.0342, -17.1062)
    arc A18 centre (-32.0454, -10.8016) radius 34.5686 from (-66.0342, -17.1062) to (-58.5154, -33.035) ccw
    line L3 (-58.5154, -33.035) -> (-44.3509, -49.8985)
    point P47 (-44.3509, -49.8985)
    arc A19 centre (-32.4623, -37.7469) radius 17 from (-44.3509, -49.8985) to (-31.2, -54.7) ccw
    point P49 (-44.3509, -49.8985)
    reference projected point E27 (-66.0256, 4.0372) from vertex [face of Pad10 from Sketch17.A5 | face of Pad10 from Sketch17.L5 | end face of Pad10]
    reference projected line E28 (-60.2, -34.45) -> (-49.1519, -47.6033) from edge [face of Pad10 from Sketch17.L2 | end face of Pad10]
    reference projected arc E29 centre (-28.0396, -7.4369) radius 42 from (-69.1412, -16.0776) to (-60.2, -34.45) ccw from edge [face of Pad10 from Sketch17.A21 | end face of Pad10]
    reference projected arc E30 centre (-74.0342, -17.1062) radius 5 from (-69.1412, -16.0775) to (-72.0998, -12.4956) ccw from edge [face of Pad10 from Sketch17.A3 | end face of Pad10]
    arc A20 centre (-54.1388, -15.5257) radius 12 from (-66.0342, -17.1062) to (-64.7862, -9.991) cw
    point P51 (-64.7862, -9.991)
    arc A21 centre (-71.4408, -6.5318) radius 7.5 from (-64.7862, -9.991) to (-64.0844, -5.0714) ccw
    point P53 (-64.7862, -9.991)
    reference projected arc E31 centre (-69.7785, -6.9628) radius 6 from (-73.6417, -2.372) to (-72.0998, -12.4956) ccw from edge [face of Pad10 from Sketch17.A4 | end face of Pad10]
    distance P3 P2 = 0
    distance E1 P1 V = 18
    distance E2 P1 = 1.5
    distance P2 E1 H = 4.5
    distance L1 E3 = 1
    distance L1 A1 = 0
    radius A1 = 7
    distance P5 E4 = 1
    radius A2 = 73
    distance A2 E4 = 1
    radius A3 = 8
    radius A4 = 12
    distance A3 E5 = 2.2
    distance A4 E6 = 2
    distance A5 E7 = 1.8
    radius A5 = 50
    distance E9 P12 = 16.4462
    distance P14 E8 = 35.5
    radius A6 = 30
    distance P16 E10 = 18
    distance P16 P18 = 0
    radius A7 = 20
    radius A8 = 15
    distance P19 E11 = 9
    distance P19 E15 V = 85
    radius A9 = 100
    distance A9 E19 = 2
    distance P21 E10 = 6
    distance P23 E19 = 2
    distance A10 E19 = 2
    radius A10 = 60
    radius A11 = 10
    radius A12 = 8
    distance P28 E20 = 14.9036
    distance P28 E21 = 10
    distance P30 E22 = 8.5
    distance P32 E23 = 2
    distance P30 E21 = 16.2762
    radius A13 = 20
    distance P33 E24 = 2
    length L2 = 22
    radius A14 = 37.4
    distance P35 P33 = 21.5
    radius A15 = 8
    distance P35 E25 = 13.5
    distance A16 E26 = 2
    distance P37 P35 = 5.5
    distance P37 E25 = 15.4
    distance P47 P49 = 0
    distance P41 P39 = 0
    radius A17 = 20
    distance E27 P39 = 4
    distance L3 E28 = 2.2
    distance P47 P1 = 14
    radius A19 = 17
    distance A18 E29 = 2.2
    distance P44 E30 H = 3
    distance P53 P51 = 0
    radius A20 = 12
    radius A21 = 7.5
    distance P44 E30 = 3
    distance P51 E31 = 11.8389
    distance P42 E31 = 12
    coincidence: P3 L1, A2 P7, P7 V, P18 A6, A11 P27, P27 A10, P49 L3
    tangency: A3 A2, A6 A5, A3 A4, A8 A7, A12 A11, L2 A13, A16 A14, A18 L3, A21 A17, A21 A20
  Pocket8: profile Sketch18, direction (1, 0, 0), length 3
  Sketch19 on end face of Pocket8, origin (-0.8, 0, 0), H (0, -1, 0), V (0, 0, 1)
    line L1 (35.4287, -51.358) -> (35.4262, -51.359)
    frozenspline C1
    frozenspline C2
    frozenspline C3
    line L2 (-13.282, -41.3496) -> (-13.3254, -41.358)
    line L3 (-13.3693, -41.3634) -> (-13.3254, -41.358)
    frozenspline C4
    line L4 (-17.337, -42.7222) -> (-32.1617, -51.5484)
    line L5 (-32.5225, -51.5468) -> (-32.1617, -51.5484)
    frozenspline C5
    line L6 (-41.9514, -47.7667) -> (-42.0053, -47.7157)
    line L7 (-42.0053, -47.7157) -> (-56.0651, -30.9769)
    frozenspline C6
    line L8 (-62.8638, -16.6508) -> (-62.8723, -16.6063)
    line L9 (-62.8776, -16.5614) -> (-62.8723, -16.6063)
    frozenspline C7
    frozenspline C8
    frozenspline C9
    line L10 (-61.2363, -0.1592) -> (-61.2306, -0.0643)
    line L11 (-61.2111, 0.0287) -> (-61.2306, -0.0643)
    frozenspline C10
    line L12 (-36.038, 45.7627) -> (-35.8814, 45.9149)
    line L13 (-35.6836, 46.0075) -> (-35.8814, 45.9149)
    frozenspline C11
    line L14 (-31.026, 50.075) -> (-30.9393, 50.2092)
    line L15 (-30.8228, 50.3184) -> (-30.9393, 50.2092)
    frozenspline C12
    line L16 (-14.0736, 58.915) -> (-13.9863, 58.9322)
    line L17 (-13.9863, 58.9322) -> (7.7671, 60.2098)
    frozenspline C13
    line L18 (22.3873, 53.2517) -> (22.3751, 53.2692)
    frozenspline C14
    frozenspline C15
    line L19 (36.284, 46.8547) -> (36.3605, 46.7901)
    line L20 (36.3605, 46.7901) -> (36.4409, 46.7304)
    frozenspline C16
    frozenspline C17
    line L21 (57.6427, 15.4989) -> (57.681, 15.3725)
    line L22 (57.6931, 15.2409) -> (57.681, 15.3725)
    frozenspline C18
    frozenspline C19
    line L23 (61.5616, 0.0007) -> (61.6156, -0.0809)
    line L24 (61.6567, -0.1697) -> (61.6156, -0.0809)
    frozenspline C20
    frozenspline C21
    line L25 (35.4297, -51.3576) -> (35.4287, -51.358)
  Pad11: profile Sketch19, direction (-1, 0, 0), length 3
  Sketch20 on end face of Pocket8, origin (-0.8, 0, 0), H (0, -1, 0), V (0, 0, 1)
    projected arc E1 centre (-32.0453, -10.8015) radius 30.0688 from (-61.5866, -16.4084) to (-55.0696, -30.1408) ccw from edge [end face of Pad11 | face of Pad11]
    projected arc E2 centre (-32.0453, -10.8015) radius 30.0688 from (-61.5866, -16.4084) to (-60.7671, -19.7) ccw from edge [end face of Pad11 | face of Pad11]
    point P1 (-61.5866, -16.4084)
    projected arc E3 centre (-54.1387, -15.5257) radius 7.5001 from (-60.7934, -12.0665) to (-61.5866, -16.4084) ccw from edge [end face of Pad11 | face of Pad11]
    point P4 (-61.5866, -16.4084)
    projected arc E4 centre (-71.4411, -6.5318) radius 12.0002 from (-60.7934, -12.0665) to (-59.6705, -4.1952) ccw from edge [end face of Pad11 | face of Pad11]
    projected arc E5 centre (-44.449, -1.1758) radius 15.5181 from (-59.9387, -0.2379) to (-59.6705, -4.1952) ccw from edge [end face of Pad11 | face of Pad11]
    projected arc E6 centre (26.1955, -18.2871) radius 88.005 from (-35.132, 44.8303) to (-59.9387, -0.2379) ccw from edge [end face of Pad11 | face of Pad11]
    projected arc E7 centre (-40.4357, 56.1496) radius 12.5001 from (-35.132, 44.8303) to (-29.9338, 49.3699) ccw from edge [end face of Pad11 | face of Pad11]
    projected arc E8 centre (-7.4349, 25.3652) radius 32.9003 from (-13.8213, 57.6397) to (-29.9338, 49.3699) ccw from edge [end face of Pad11 | face of Pad11]
    projected line E9 (7.8433, 58.912) -> (-13.8213, 57.6397) from edge [end face of Pad11 | face of Pad11]
    projected arc E10 centre (8.7524, 43.4409) radius 15.4978 from (21.3206, 52.5086) to (7.8433, 58.912) ccw from edge [end face of Pad11 | face of Pad11]
    projected arc E11 centre (31.5752, 59.6552) radius 12.4992 from (21.3206, 52.5086) to (31.7989, 47.158) ccw from edge [end face of Pad11 | face of Pad11]
    projected arc E14 centre (-35.0037, -12.5706) radius 95.5052 from (56.3985, 15.122) to (54.7317, 20.1218) ccw from edge [end face of Pad11 | face of Pad11]
    projected arc E15 centre (45.9394, 14.1611) radius 10.5032 from (56.4345, 13.7508) to (56.3985, 15.122) ccw from edge [end face of Pad11 | face of Pad11]
    projected arc E16 centre (80.9162, 12.7936) radius 24.5003 from (56.4345, 13.7508) to (60.4771, -0.7161) ccw from edge [end face of Pad11 | face of Pad11]
    projected arc E17 centre (37.3387, -11.4344) radius 25.5003 from (62.4774, -15.7141) to (60.4771, -0.7161) ccw from edge [end face of Pad11 | face of Pad11]
    point P31 (62.4774, -15.7141)
    projected arc E18 centre (17.6229, -8.0777) radius 45.4999 from (34.9341, -50.1558) to (62.4774, -15.7141) ccw from edge [end face of Pad11 | face of Pad11]
    projected arc E19 centre (17.6229, -8.0777) radius 45.4999 from (48.9451, -41.08) to (62.4774, -15.7141) ccw from edge [end face of Pad11 | face of Pad11]
    point P34 (62.4774, -15.7141)
    offset arc E20 centre (17.6227, -8.0775) radius 41.5001 from (33.4122, -46.4566) to (58.5341, -15.0428) ccw from edge [end face of Pad11 | face of Pad11]
    offset arc E21 centre (17.6227, -8.0775) radius 41.5001 from (45.4892, -38.83) to (58.5341, -15.0428) ccw from edge [end face of Pad11 | face of Pad11]
    point P36 (58.5341, -15.0428)
    offset arc E22 centre (37.3365, -11.4347) radius 21.5025 from (58.5341, -15.0428) to (56.8476, -2.3974) ccw from edge [end face of Pad11 | face of Pad11]
    offset arc E23 centre (37.3365, -11.4347) radius 21.5025 from (58.5341, -15.0428) to (56.9624, -2.6494) ccw from edge [end face of Pad11 | face of Pad11]
    point P37 (58.5341, -15.0428)
    offset arc E24 centre (80.9165, 12.7936) radius 28.5006 from (52.4376, 13.9071) to (57.1402, -2.9218) ccw from edge [end face of Pad11 | face of Pad11]
    offset arc E25 centre (80.9165, 12.7936) radius 28.5006 from (52.4376, 13.9071) to (56.9624, -2.6494) ccw from edge [end face of Pad11 | face of Pad11]
    point P39 (52.4376, 13.9071)
    point P41 (56.9624, -2.6494)
    offset arc E26 centre (45.939, 14.1611) radius 6.5035 from (52.4376, 13.9071) to (52.4153, 14.7559) ccw from edge [end face of Pad11 | face of Pad11]
    offset arc E27 centre (45.939, 14.1611) radius 6.5035 from (52.4376, 13.9071) to (52.4384, 14.3939) ccw from edge [end face of Pad11 | face of Pad11]
    point P42 (52.4376, 13.9071)
    offset arc E28 centre (-35.0097, -12.5726) radius 91.5115 from (52.5704, 13.9622) to (50.9734, 18.7526) ccw from edge [end face of Pad11 | face of Pad11]
    offset arc E29 centre (-35.0097, -12.5726) radius 91.5115 from (52.4384, 14.3939) to (50.9734, 18.7526) ccw from edge [end face of Pad11 | face of Pad11]
    point P46 (52.4384, 14.3939)
    point P47 (52.4384, 14.3939)
    line L1 (33.1688, 42.5588) -> (32.9726, 42.7142)
    offset arc E32 centre (31.5752, 59.6552) radius 16.4993 from (18.0387, 50.2219) to (31.8705, 43.1586) ccw from edge [end face of Pad11 | face of Pad11]
    offset line E33 (8.0778, 54.9189) -> (-13.5868, 53.6466) from edge [end face of Pad11 | face of Pad11]
    offset line E34 (8.0778, 54.9189) -> (-13.3045, 53.6631) from edge [end face of Pad11 | face of Pad11]
    arc A1 centre (8.752, 43.4382) radius 11.5005 from (8.0778, 54.9189) to (18.0387, 50.2219) cw
    offset arc E35 centre (-7.4339, 25.3633) radius 28.9024 from (-13.0448, 53.7158) to (-27.1984, 46.4515) ccw from edge [end face of Pad11 | face of Pad11]
    offset arc E36 centre (-7.4339, 25.3633) radius 28.9024 from (-13.3045, 53.6631) to (-26.8741, 46.7508) ccw from edge [end face of Pad11 | face of Pad11]
    point P59 (-13.3045, 53.6631)
    offset arc E37 centre (-40.4358, 56.1497) radius 16.5003 from (-33.4349, 41.2082) to (-26.5732, 47.2005) ccw from edge [end face of Pad11 | face of Pad11]
    offset arc E38 centre (-40.4358, 56.1497) radius 16.5003 from (-32.7852, 41.5302) to (-26.8741, 46.7508) ccw from edge [end face of Pad11 | face of Pad11]
    point P62 (-26.8741, 46.7508)
    offset arc E39 centre (26.1964, -18.2876) radius 84.006 from (-32.3446, 41.9615) to (-56.0238, -1.0583) ccw from edge [end face of Pad11 | face of Pad11]
    offset arc E40 centre (26.1964, -18.2876) radius 84.006 from (-32.7852, 41.5302) to (-55.9594, -0.7538) ccw from edge [end face of Pad11 | face of Pad11]
    point P65 (-32.7852, 41.5302)
    offset arc E41 centre (-44.449, -1.1758) radius 11.5181 from (-55.9461, -0.4803) to (-55.7471, -3.4163) ccw from edge [end face of Pad11 | face of Pad11]
    offset arc E42 centre (-44.449, -1.1758) radius 11.5181 from (-55.9594, -0.7538) to (-55.7471, -3.4163) ccw from edge [end face of Pad11 | face of Pad11]
    point P67 (-55.7471, -3.4163)
    point P68 (-55.9594, -0.7538)
    point P69 (-55.9594, -0.7538)
    offset arc E43 centre (-71.4411, -6.5318) radius 16.0003 from (-57.2443, -13.9114) to (-55.7471, -3.4163) ccw from edge [end face of Pad11 | face of Pad11]
    point P70 (-57.2443, -13.9114)
    point P71 (-55.7471, -3.4163)
    point P72 (-56.1682, -1.7625)
    offset arc E44 centre (-54.1383, -15.5258) radius 3.5004 from (-57.2443, -13.9114) to (-57.6144, -15.9376) ccw from edge [end face of Pad11 | face of Pad11]
    offset arc E45 centre (-54.1383, -15.5258) radius 3.5004 from (-57.2443, -13.9114) to (-57.6263, -15.8203) ccw from edge [end face of Pad11 | face of Pad11]
    point P73 (-57.2443, -13.9114)
    offset arc E46 centre (-32.0438, -10.8008) radius 26.0704 from (-57.6568, -15.6625) to (-52.0068, -27.5681) ccw from edge [end face of Pad11 | face of Pad11]
    offset arc E47 centre (-32.0438, -10.8008) radius 26.0704 from (-57.6263, -15.8203) to (-56.1616, -20.7) ccw from edge [end face of Pad11 | face of Pad11]
    point P77 (-57.6263, -15.8203)
    point P78 (-57.6263, -15.8203)
    line L2 (-56.1616, -20.7) -> (-60.7671, -19.7)
    point P79 (-56.1616, -20.7)
    reference projected arc E48 centre (-26.45, -66.45) radius 6.25 from (-32.7, -66.45) to (-20.2, -66.45) ccw from edge [face of Pad10 from Sketch17.A1 | end face of Pad10]
    point P80 (-60.7671, -19.7)
    line L3 (48.9451, -41.08) -> (45.4892, -38.83)
    point P81 (48.9451, -41.08)
    point P82 (45.4892, -38.83)
    reference projected arc E49 centre (26.2, -66.08) radius 6 from (20.2, -66.08) to (31.7249, -63.7401) ccw from edge [face of Pad10 from Sketch17.A17 | end face of Pad10]
    distance P79 E48 V = 52
    distance P80 E48 V = 53
    distance P81 E49 V = 31
    distance P82 E49 V = 33.25
    coincidence: E24 P41, E26 P46, E28 P47, E33 P59, E35 P62, E39 P65, E41 P68, E39 P69, E43 P72, P72 E39, E44 P77, E46 P78, P79 E46, E1 P80, P81 E18, P82 E20, P1 P4, P31 P34, P36 P37, P39 P42, P46 P47, P67 P71, P68 P69, P70 P73, P77 P78
    tangency: A1 E33
  Pad12: profile Sketch20, direction (-1, 0, 0), length 3
  Sketch21 on end face of Pocket8, origin (-0.8, 0, 0), H (0, -1, 0), V (0, 0, 1)
    projected arc E1 centre (1.1745, -116.1659) radius 77.5002 from (16.8977, -40.2774) to (-13.5286, -40.0732) ccw from edge [end face of Pad11 | face of Pad11]
    projected arc E2 centre (14.3612, -52.5181) radius 12.5007 from (25.4301, -46.7089) to (16.8977, -40.2774) ccw from edge [end face of Pad11 | face of Pad11]
    projected line E3 (-32.5168, -50.2468) -> (-18.002, -41.6052) from edge [end face of Pad11 | face of Pad11]
    projected line E4 (-19.8409, -42.7) -> (-18.002, -41.6052) from edge [end face of Pad11 | face of Pad11]
    point P6 (-18.002, -41.6052)
    projected arc E5 centre (-12.1076, -51.5199) radius 11.5346 from (-13.5286, -40.0732) to (-18.002, -41.6052) ccw from edge [end face of Pad11 | face of Pad11]
    point P8 (-18.002, -41.6052)
    offset arc E6 centre (1.1744, -116.1678) radius 81.5021 from (17.7092, -36.3606) to (-14.2875, -36.1459) ccw from edge [end face of Pad11 | face of Pad11]
    offset arc E7 centre (1.1744, -116.1678) radius 81.5021 from (17.7092, -36.3606) to (-14.1632, -36.1219) ccw from edge [end face of Pad11 | face of Pad11]
    point P10 (-14.2875, -36.1459)
    offset arc E8 centre (-12.1074, -51.5204) radius 15.5351 from (-14.0189, -36.1034) to (-20.0483, -38.1682) ccw from edge [end face of Pad11 | face of Pad11]
    offset arc E9 centre (-12.1074, -51.5204) radius 15.5351 from (-14.1632, -36.1219) to (-20.0483, -38.1682) ccw from edge [end face of Pad11 | face of Pad11]
    point P13 (-16.2892, -36.5587)
    point P14 (-14.1632, -36.1219)
    offset line E10 (-34.5631, -46.8098) -> (-20.0483, -38.1682) from edge [end face of Pad11 | face of Pad11]
    offset line E11 (-21.7813, -39.2) -> (-20.0483, -38.1682) from edge [end face of Pad11 | face of Pad11]
    line L1 (-19.8409, -42.7) -> (-21.7813, -39.2)
    point P18 (-19.8409, -42.7)
    point P19 (-21.7813, -39.2)
    line L2 (25.8877, -47.68) -> (28.2315, -43.58)
    point P20 (25.8877, -47.68)
    point P21 (28.2315, -43.58)
    reference projected arc E12 centre (26.2, -66.08) radius 6 from (20.2, -66.08) to (31.7249, -63.7401) ccw from edge [face of Pad10 from Sketch17.A17 | end face of Pad10]
    reference projected arc E13 centre (-26.45, -66.45) radius 6.25 from (-32.7, -66.45) to (-20.2, -66.45) ccw from edge [face of Pad10 from Sketch17.A1 | end face of Pad10]
    reference projected line E14 (20.2, -52.2166) -> (20.2, -66.08) from edge [face of Pad10 from Sketch17.L6 | end face of Pad10]
    line L3 (25.4301, -46.7089) -> (25.8877, -47.68)
    arc A1 centre (14.3618, -52.5172) radius 16.4997 from (17.7092, -36.3606) to (28.2315, -43.58) cw
    distance P21 E12 V = 28.5
    distance P20 E12 V = 24.4
    distance P18 E13 V = 30
    distance P19 E13 V = 33.5
    distance P21 E14 = 8.0315
    angle L3 L2 = 125.0156
    coincidence: E8 P13, P13 E6, E8 P10, E8 P14, P18 E3, P19 E10, P20 E2, P6 P8
    tangency: E10 E8, A1 E6
  Pad13: profile Sketch21, direction (-1, 0, 0), length 3
  Sketch22 on xy-plane, origin (0, 0, 0), H (1, 0, 0), V (0, 1, 0)
    point P1 (-5.8, 60.5611)
    line L1 (-3.8, 61.2111) -> (-3.8, 59.9111)
    line L2 (-3.8, 59.9111) -> (-7.8, 59.9111)
    line L3 (-7.8, 59.9111) -> (-7.8, 61.2111)
    line L4 (-7.8, 61.2111) -> (-3.8, 61.2111)
    reference projected line E1 (-3.8, 61.2671) -> (-3.8, 60.9456) from edge [face of Pad11 from Sketch19.C9 | end face of Pad11]
    reference projected line E2 (-0.8, 61.2111) -> (-3.8, 61.2111) from edge [face of Pad11 from Sketch19.L11 | face of Pad11 from Sketch19.C10]
    length L4 = 4
    distance L1 E1 = 0
    distance E2 L4 = 0
    length L3 = 1.3
    vertical: L1 V, L3 V
    horizontal: L2 H, L4 H
    equidistance: L1 L3 P1, L2 L4 P1
  Sketch23 on face of Pad13, origin (-3.8, 0, 0), H (0, -1, 0), V (0, 0, 1)
    offset arc E1 centre (-44.4489, -1.1757) radius 16.1682 from (-60.5875, -0.1986) to (-60.3081, -4.3218) ccw from edge [face of Pad11 from Sketch19.C9 | face of Pad13]
    offset arc E2 centre (-71.4436, -6.5314) radius 11.3527 from (-61.3701, -11.7667) to (-60.3081, -4.3218) ccw from edge [face of Pad11 from Sketch19.C8 | face of Pad13]
    point P3 (-61.3701, -11.7667)
    offset arc E3 centre (-54.1355, -15.5263) radius 8.1532 from (-61.3701, -11.7667) to (-62.2321, -16.4849) ccw from edge [face of Pad11 from Sketch19.C7 | face of Pad13]
    point P5 (-61.3701, -11.7667)
    offset arc E4 centre (-32.0417, -10.7998) radius 30.7369 from (-62.2394, -16.5322) to (-55.5784, -30.5681) ccw from edge [face of Pad11 from Sketch19.C6 | face of Pad13]
    offset arc E5 centre (-32.0417, -10.7998) radius 30.7369 from (-62.2394, -16.5322) to (-59.747, -24.1106) ccw from edge [face of Pad11 from Sketch19.C6 | face of Pad13]
    line L1 (-62.2394, -16.5322) -> (-62.2321, -16.4849)
    offset arc E6 centre (26.197, -18.2879) radius 88.6566 from (-35.585, 45.2965) to (-60.5749, -0.1046) ccw from edge [face of Pad11 from Sketch19.C10 | face of Pad13]
    line L2 (-60.5875, -0.1986) -> (-60.5749, -0.1046)
    offset arc E7 centre (-40.437, 56.1511) radius 11.8521 from (-35.4078, 45.4189) to (-30.4799, 49.7225) ccw from edge [face of Pad11 from Sketch19.C11 | face of Pad13]
    offset arc E8 centre (-40.437, 56.1511) radius 11.8521 from (-35.4078, 45.4189) to (-32.4232, 47.4189) ccw from edge [face of Pad11 from Sketch19.C11 | face of Pad13]
    line L3 (-35.585, 45.2965) -> (-35.4078, 45.4189)
    tangency: E2 E1, E3 E2
    coincidence: P5 P3, E3 P3
  Rib1: profile Sketch22, centre curve Sketch23
  Chamfer1: length 4, angle 45, on edge [face of Rib1 | face of Rib1]
  Chamfer2: length 4, angle 45, on edge [face of Rib1 | face of Rib1]
  Fillet8: radius 0.5, on edge [face of Chamfer2 | face of Pad13]; edge [face of Rib1 | face of Chamfer2]
  Fillet9: radius 0.5, on edge [face of Chamfer1 | face of Rib1]; edge [face of Pad13 | face of Chamfer1]
  Sketch24 on xy-plane, origin (0, 0, 0), H (1, 0, 0), V (0, 1, 0)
